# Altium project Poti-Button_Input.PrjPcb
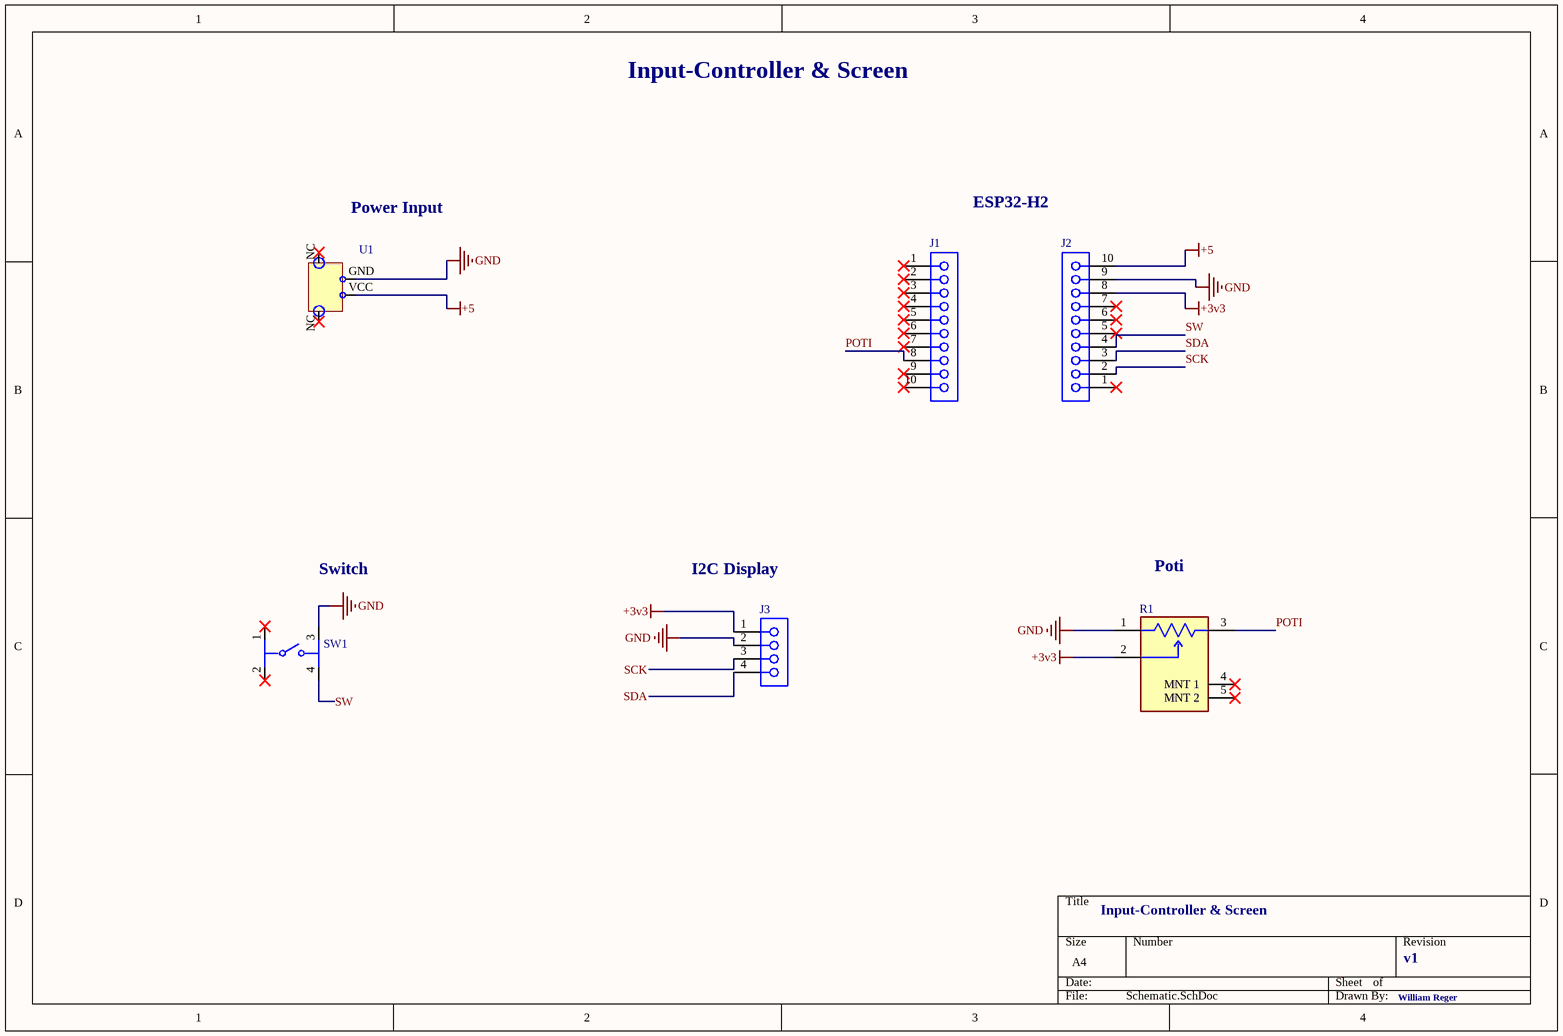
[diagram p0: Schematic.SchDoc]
1 sheet, 6 parts. Net scope: global (net labels, ports and power ports of the same name join across sheets).
Board file: PCB2.PcbDoc

## Sheet Schematic.SchDoc
size A4; SheetNumber: 1; SheetTotal: 1

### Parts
J1  SSW-110-03-G-S  [SMTC-SSW-110-03-X-S]  (value not drawn)
J2  SSW-110-03-G-S  [SMTC-SSW-110-03-X-S]  (value not drawn)
J3  SLW-104-01-G-S  [SMTC-SLW-104-01-X-S]  (value not drawn)
R1  PTV09A-4225F-B102  [FP-PTV09A-4-MFG]  (value not drawn)
SW1  3-1825910-1  [FP-3-1825910-1-MFG]  (value not drawn)
U1  USB Type C 2 Pin Connector  [USB C Power Connector]  (value not drawn)

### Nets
+3v3: J2.8 J3.1 R1.2
+5: J2.10 U1.VCC
GND: J2.9 J3.2 R1.1 SW1.3 U1.GND
POTI: J1.8 R1.3
SCK: J2.2 J3.3
SDA: J2.3 J3.4
SW: J2.4 SW1.4

Not connected (* = marked no-connect by the designer): J1 1* 2* 3* 4* 5* 6* 7* 9* 10*; J2 1* 5* 6* 7*; R1 4(MNT_1)* 5(MNT_2)*; SW1 1* 2*; U1 NC*

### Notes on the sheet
- Input-Controller & Screen
- (near U1) Power Input
- ESP32-H2
- Switch
- (near J3) I2C Display
- Poti
- v1
- William Reger

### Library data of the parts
J1 J2 = CMP-1023-00394-1: SQ Post Socket, Through-hole, Vertical, -55 to 125 degC, 2.54 mm Pitch, 10-Pin, Female, RoHS; Manufacturer: Samtec; Pitch: 2.54 mm
J3 = CMP-1023-00130-1: Low Profile Socket Strips, Through-hole, Vertical, -55 to 125 degC, 2.54 mm Pitch, 4-Pin, Female, RoHS; Manufacturer: Samtec; Pitch: 2.54 mm
R1 = CMP-07234-000055-1: POT 1K OHM 1/20W CARBON LINEAR; Tolerance: 20%; Max Power Dissipation: 50mW; Actuator Length: 0.984inch; Number of Turns: 1; Resistance: 1kR; Actuator Diameter: 0.236inch
SW1 = CMP-03407-000001-1: SWITCH TACTILE SPST-NO 0.05A 24V; Manufacturer: TE Connectivity; Operating Force: 160gf; Contact Current Rating: 50mA; Description: Switch Tactile OFF (ON) SPST Round Button PC Pins 0.05A 24VDC 100000Cycles 1.57N Thru-Hole; Contact Resistance: 100mΩ; Electromechanical Life: 100000Cycles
